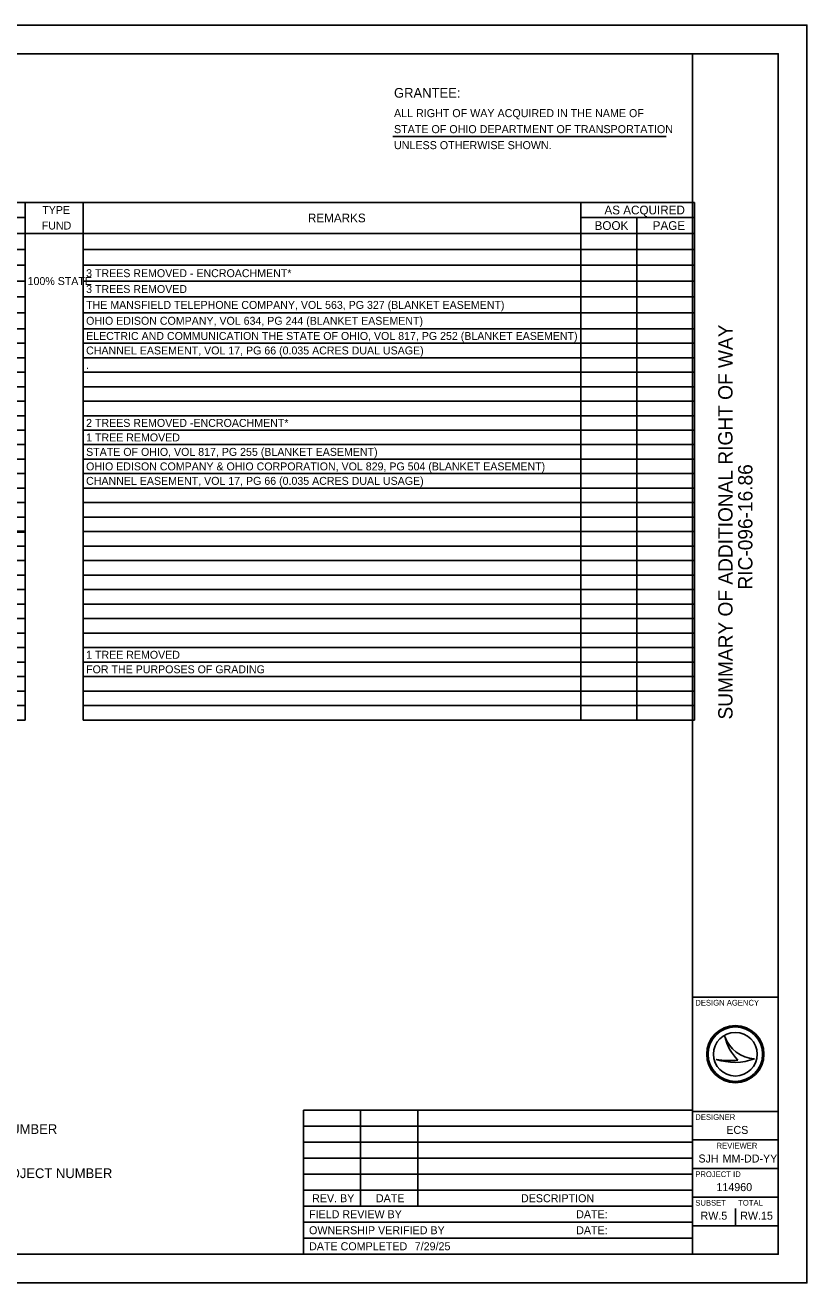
# Model space of a CAD drawing. Extents: x 0 to 34, y 0 to 22.
# Drawn here: x 20.33 to 34, y 0 to 22 of the extents above; entities that cross this region are included whole.
import ezdxf

# ---------------------------------------------------------------- set-up
doc = ezdxf.new("R2010")
doc.units = 0
for name, color, linetype in [('SH_Border', 7, 'Continuous'), ('SH_Cut_Line', 7, 'Continuous'), ('SH_Data', 7, 'Continuous'), ('SH_Text', 7, 'Continuous')]:
    doc.layers.add(name, color=color, linetype=linetype)

msp = doc.modelspace()

# ---------------------------------------------------------------- linework, layer by layer
at = {"layer": 'SH_Border'}
for p, q in [((32, 0.5), (32, 21.5)), ((32, 5), (33.5, 5)), ((32, 3), (33.5, 3)), ((32, 2.5), (33.5, 2.5)), ((32, 2), (33.5, 2)), ((32, 1.5), (33.5, 1.5)), ((32, 1), (33.5, 1))]:
    msp.add_line(p, q, dxfattribs=at)
msp.add_lwpolyline([(1.5, 21.5), (33.5, 21.5), (33.5, 0.5), (1.5, 0.5)], close=True, dxfattribs=at)
at = {"layer": 'SH_Cut_Line'}
msp.add_lwpolyline([(0, 0), (34, 0), (34, 22), (0, 22)], close=True, dxfattribs=at)
at = {"layer": 'SH_Data'}
for p, q in [((32.567, 4.31), (32.567, 4.31)), ((32.75, 4), (32.75, 4)), ((32.417, 3.91), (32.417, 3.91)), ((33.087, 3.919), (33.087, 3.919)), ((32.75, 1), (32.75, 1.3))]:
    msp.add_line(p, q, dxfattribs=at)
for radius in [0.5, 0.477, 0.477, 0.382]:
    msp.add_circle((32.75, 4), radius, dxfattribs=at)
for centre, radius, start, end in [((33.116, 4.498), 0.58, 198.9257, 198.9319), ((33.347, 4.47), 0.796, 191.6379, 191.6421), ((33.116, 4.498), 0.58, 198.9319, 267.1657), ((33.347, 4.47), 0.796, 191.6421, 226.0947), ((32.739, 4.87), 1.013, 251.4576, 290.0832), ((32.648, 5.154), 1.266, 259.4964, 259.4995), ((32.739, 4.87), 1.013, 251.4527, 251.4576), ((32.648, 5.154), 1.266, 259.4995, 276.6672)]:
    msp.add_arc(centre, radius, start, end, dxfattribs=at)
at = {"layer": 'SH_Text'}
for p, q in [((26.76, 20.055), (31.541, 20.055)), ((7.67, 18.899), (20.333, 18.899)), ((20.333, 18.899), (21.346, 18.899)), ((20.333, 18.899), (20.333, 18.634)), ((21.346, 18.899), (32.038, 18.899)), ((21.346, 18.899), (21.346, 18.634)), ((30.046, 18.899), (30.046, 18.634)), ((32.038, 18.899), (32.038, 18.634)), ((18.287, 18.634), (20.333, 18.634)), ((20.333, 18.634), (20.333, 18.078)), ((21.346, 18.634), (21.346, 18.078)), ((30.046, 18.634), (32.038, 18.634)), ((30.046, 18.634), (30.046, 18.078)), ((31.026, 18.634), (31.026, 18.078)), ((32.038, 18.634), (32.038, 18.078)), ((7.67, 18.356), (20.333, 18.356)), ((20.333, 18.356), (21.346, 18.356)), ((21.346, 18.356), (32.038, 18.356)), ((7.67, 18.078), (20.333, 18.078)), ((20.333, 18.078), (20.333, 17.801)), ((21.346, 18.078), (32.038, 18.078)), ((21.346, 18.078), (21.346, 17.801)), ((30.046, 18.078), (30.046, 17.801)), ((31.026, 18.078), (31.026, 17.801)), ((32.038, 18.078), (32.038, 17.801)), ((7.67, 17.801), (20.333, 17.801)), ((20.333, 17.801), (20.333, 17.523)), ((21.346, 17.801), (32.038, 17.801)), ((21.346, 17.801), (21.346, 17.523)), ((30.046, 17.801), (30.046, 17.523)), ((31.026, 17.801), (31.026, 17.523)), ((32.038, 17.801), (32.038, 17.523)), ((7.67, 17.523), (20.333, 17.523)), ((20.333, 17.523), (20.333, 17.245)), ((21.346, 17.523), (32.038, 17.523)), ((21.346, 17.523), (21.346, 17.245)), ((30.046, 17.523), (30.046, 17.245)), ((31.026, 17.523), (31.026, 17.245)), ((32.038, 17.523), (32.038, 17.245)), ((7.67, 17.245), (20.333, 17.245)), ((20.333, 17.245), (20.333, 16.69)), ((21.346, 17.245), (32.038, 17.245)), ((21.346, 17.245), (21.346, 16.69)), ((30.046, 17.245), (30.046, 16.69)), ((31.026, 17.245), (31.026, 16.69)), ((32.038, 17.245), (32.038, 16.69)), ((7.67, 16.968), (20.333, 16.968)), ((21.346, 16.968), (32.038, 16.968)), ((7.67, 16.69), (20.333, 16.69)), ((20.333, 16.69), (20.333, 16.437)), ((21.346, 16.69), (32.038, 16.69)), ((21.346, 16.69), (21.346, 16.437)), ((30.046, 16.69), (30.046, 16.437)), ((31.026, 16.69), (31.026, 16.437)), ((32.038, 16.69), (32.038, 16.437)), ((7.67, 16.437), (20.333, 16.437)), ((20.333, 16.437), (20.333, 15.676)), ((21.346, 16.437), (32.038, 16.437)), ((21.346, 16.437), (21.346, 15.676)), ((30.046, 16.437), (30.046, 15.676)), ((31.026, 16.437), (31.026, 15.676)), ((32.038, 16.437), (32.038, 15.676)), ((7.67, 16.183), (20.333, 16.183)), ((21.346, 16.183), (32.038, 16.183)), ((7.67, 15.93), (20.333, 15.93)), ((21.346, 15.93), (32.038, 15.93)), ((7.67, 15.676), (20.333, 15.676)), ((20.333, 15.676), (20.333, 15.423)), ((21.346, 15.676), (32.038, 15.676)), ((21.346, 15.676), (21.346, 15.423)), ((30.046, 15.676), (30.046, 15.423)), ((31.026, 15.676), (31.026, 15.423)), ((32.038, 15.676), (32.038, 15.423)), ((7.67, 15.423), (20.333, 15.423)), ((20.333, 15.423), (20.333, 14.662)), ((21.346, 15.423), (32.038, 15.423)), ((21.346, 15.423), (21.346, 14.662)), ((30.046, 15.423), (30.046, 14.662)), ((31.026, 15.423), (31.026, 14.662)), ((32.038, 15.423), (32.038, 14.662)), ((7.67, 15.169), (20.333, 15.169)), ((21.346, 15.169), (32.038, 15.169)), ((7.67, 14.916), (20.333, 14.916)), ((21.346, 14.916), (32.038, 14.916)), ((7.67, 14.662), (20.333, 14.662)), ((20.333, 14.662), (20.333, 14.408)), ((21.346, 14.662), (32.038, 14.662)), ((21.346, 14.662), (21.346, 14.408)), ((30.046, 14.662), (30.046, 14.408)), ((31.026, 14.662), (31.026, 14.408)), ((32.038, 14.662), (32.038, 14.408)), ((7.67, 14.408), (20.333, 14.408)), ((20.333, 14.408), (20.333, 13.901)), ((21.346, 14.408), (32.038, 14.408)), ((21.346, 14.408), (21.346, 13.901)), ((30.046, 14.408), (30.046, 13.901)), ((31.026, 14.408), (31.026, 13.901)), ((32.038, 14.408), (32.038, 13.901)), ((7.67, 14.155), (20.333, 14.155)), ((21.346, 14.155), (32.038, 14.155)), ((7.67, 13.901), (20.333, 13.901)), ((20.333, 13.901), (20.333, 13.648)), ((21.346, 13.901), (32.038, 13.901)), ((21.346, 13.901), (21.346, 13.648)), ((30.046, 13.901), (30.046, 13.648)), ((31.026, 13.901), (31.026, 13.648)), ((32.038, 13.901), (32.038, 13.648)), ((7.67, 13.648), (20.333, 13.648)), ((20.333, 13.648), (20.333, 13.394)), ((21.346, 13.648), (32.038, 13.648)), ((21.346, 13.648), (21.346, 13.394)), ((30.046, 13.648), (30.046, 13.394)), ((31.026, 13.648), (31.026, 13.394)), ((32.038, 13.648), (32.038, 13.394)), ((7.67, 13.394), (20.333, 13.394)), ((20.333, 13.394), (20.333, 13.131)), ((21.346, 13.394), (32.038, 13.394)), ((21.346, 13.394), (21.346, 13.141)), ((30.046, 13.394), (30.046, 13.141)), ((31.026, 13.394), (31.026, 13.141)), ((32.038, 13.394), (32.038, 13.141)), ((12.483, 13.151), (20.333, 13.151)), ((12.483, 13.131), (20.333, 13.131)), ((20.333, 13.151), (20.333, 12.634)), ((21.346, 13.141), (32.038, 13.141)), ((21.346, 13.141), (21.346, 12.634)), ((30.046, 13.141), (30.046, 12.634)), ((31.026, 13.141), (31.026, 12.634)), ((32.038, 13.141), (32.038, 12.634)), ((7.67, 12.887), (20.333, 12.887)), ((21.346, 12.887), (32.038, 12.887)), ((7.67, 12.634), (20.333, 12.634)), ((20.333, 12.634), (20.333, 12.38)), ((21.346, 12.634), (32.038, 12.634)), ((21.346, 12.634), (21.346, 12.38)), ((30.046, 12.634), (30.046, 12.38)), ((31.026, 12.634), (31.026, 12.38)), ((32.038, 12.634), (32.038, 12.38)), ((7.67, 12.38), (20.333, 12.38)), ((20.333, 12.38), (20.333, 12.127)), ((21.346, 12.38), (32.038, 12.38)), ((21.346, 12.38), (21.346, 12.127)), ((30.046, 12.38), (30.046, 12.127)), ((31.026, 12.38), (31.026, 12.127)), ((32.038, 12.38), (32.038, 12.127)), ((7.67, 12.127), (20.333, 12.127)), ((20.333, 12.127), (20.333, 11.873)), ((21.346, 12.127), (32.038, 12.127)), ((21.346, 12.127), (21.346, 11.873)), ((30.046, 12.127), (30.046, 11.873)), ((31.026, 12.127), (31.026, 11.873)), ((32.038, 12.127), (32.038, 11.873)), ((7.67, 11.873), (20.333, 11.873)), ((20.333, 11.873), (20.333, 9.845)), ((21.346, 11.873), (32.038, 11.873)), ((21.346, 11.873), (21.346, 9.845)), ((30.046, 11.873), (30.046, 9.845)), ((31.026, 11.873), (31.026, 9.845)), ((32.038, 11.873), (32.038, 9.845)), ((7.67, 11.62), (20.333, 11.62)), ((21.346, 11.62), (32.038, 11.62)), ((7.67, 11.366), (20.333, 11.366)), ((21.346, 11.366), (32.038, 11.366)), ((7.67, 11.113), (20.333, 11.113)), ((21.346, 11.113), (32.038, 11.113)), ((7.67, 10.859), (20.333, 10.859)), ((21.346, 10.859), (32.038, 10.859)), ((7.67, 10.606), (20.333, 10.606)), ((21.346, 10.606), (32.038, 10.606)), ((7.67, 10.352), (20.333, 10.352)), ((21.346, 10.352), (32.038, 10.352)), ((7.67, 10.099), (20.333, 10.099)), ((21.346, 10.099), (32.038, 10.099)), ((7.67, 9.845), (20.333, 9.845)), ((21.346, 9.845), (32.038, 9.845)), ((25.197, 3.02), (25.197, 0.5)), ((25.197, 3.02), (32, 3.02)), ((26.197, 3.02), (26.197, 1.34)), ((27.197, 3.02), (27.197, 1.34)), ((25.197, 2.74), (32, 2.74)), ((25.197, 2.46), (32, 2.46)), ((25.197, 2.18), (32, 2.18)), ((25.197, 1.9), (32, 1.9)), ((25.197, 1.62), (32, 1.62)), ((25.197, 1.34), (32, 1.34)), ((25.197, 1.06), (32, 1.06)), ((25.197, 0.78), (32, 0.78)), ((32, 0.5), (32, 0.5))]:
    msp.add_line(p, q, dxfattribs=at)

# ---------------------------------------------------------------- texts
at = {"layer": 'SH_Data'}
for s, p in [('SUMMARY OF ADDITIONAL RIGHT OF WAY', (32.701, 9.854)), ('RIC-096-16.86', (33.049, 12.127))]:
    msp.add_text(s, height=0.25, rotation=90, dxfattribs=at).set_placement(p)
for s, height, p in [('DESIGN AGENCY', 0.1, (32.05, 4.85)), ('DESIGNER', 0.1, (32.05, 2.85)), ('ECS', 0.14, (32.592, 2.605)), ('REVIEWER', 0.1, (32.422, 2.35)), ('SJH', 0.14, (32.105, 2.105)), ('MM-DD-YY', 0.14, (32.527, 2.105)), ('PROJECT ID', 0.1, (32.05, 1.85)), ('SUBSET', 0.1, (32.05, 1.35)), ('TOTAL', 0.1, (32.8, 1.35)), ('RW.5', 0.14, (32.141, 1.105)), ('RW.15', 0.14, (32.835, 1.105))]:
    msp.add_text(s, height=height, dxfattribs=at).set_placement(p)
at = {"layer": 'SH_Text'}
for s, height, p in [('GRANTEE:', 0.17, (26.782, 20.731)), ('ALL RIGHT OF WAY ACQUIRED IN THE NAME OF', 0.14, (26.782, 20.391)), ('STATE OF OHIO DEPARTMENT OF TRANSPORTATION     ', 0.14, (26.782, 20.111)), ('UNLESS OTHERWISE SHOWN.', 0.14, (26.782, 19.831)), ('TYPE', 0.1388, (20.633, 18.697)), ('REMARKS', 0.1527, (25.277, 18.551)), ('AS ACQUIRED', 0.15271, (30.461, 18.69)), ('FUND', 0.1388, (20.624, 18.425)), ('BOOK', 0.1527, (30.289, 18.418)), ('PAGE', 0.1527, (31.305, 18.418)), ('3 TREES REMOVED - ENCROACHMENT*', 0.13883, (21.399, 17.592)), ('100% STATE', 0.1388, (20.376, 17.454)), ('3 TREES REMOVED', 0.13883, (21.399, 17.315)), ('THE MANSFIELD TELEPHONE COMPANY, VOL 563, PG 327 (BLANKET EASEMENT)', 0.13883, (21.399, 17.037)), ('OHIO EDISON COMPANY, VOL 634, PG 244 (BLANKET EASEMENT)', 0.13883, (21.399, 16.759)), ('ELECTRIC AND COMMUNICATION THE STATE OF OHIO, VOL 817, PG 252 (BLANKET EASEMENT)', 0.13883, (21.399, 16.494)), ('CHANNEL EASEMENT, VOL 17, PG 66 (0.035 ACRES DUAL USAGE)', 0.13883, (21.399, 16.24)), ('.', 0.139, (21.399, 15.987)), ('2 TREES REMOVED -ENCROACHMENT*', 0.13883, (21.399, 14.973)), ('1 TREE REMOVED', 0.13883, (21.399, 14.719)), ('STATE OF OHIO, VOL 817, PG 255 (BLANKET EASEMENT)', 0.13883, (21.399, 14.466)), ('OHIO EDISON COMPANY & OHIO CORPORATION, VOL 829, PG 504 (BLANKET EASEMENT)', 0.13883, (21.399, 14.212)), ('CHANNEL EASEMENT, VOL 17, PG 66 (0.035 ACRES DUAL USAGE)', 0.13883, (21.399, 13.959)), ('1 TREE REMOVED', 0.13883, (21.399, 10.917)), ('FOR THE PURPOSES OF GRADING', 0.13883, (21.399, 10.663)), ('STATE JOB NUMBER', 0.17, (18.608, 2.605)), ('FEDERAL PROJECT NUMBER', 0.17, (18.636, 1.832)), ('REV. BY', 0.14, (25.35, 1.41)), ('DATE', 0.14, (26.466, 1.41)), ('DESCRIPTION', 0.14, (29.002, 1.41)), ('114960', 0.14, (32.419, 1.605)), ('FIELD REVIEW BY', 0.14, (25.297, 1.13)), ('DATE:', 0.14, (29.967, 1.13)), ('OWNERSHIP VERIFIED BY', 0.14, (25.297, 0.85)), ('DATE:', 0.14, (29.967, 0.85)), ('DATE COMPLETED', 0.14, (25.297, 0.57)), ('7/29/25                             ', 0.14, (27.144, 0.57))]:
    msp.add_text(s, height=height, dxfattribs=at).set_placement(p)

doc.saveas('drawing.dxf')
